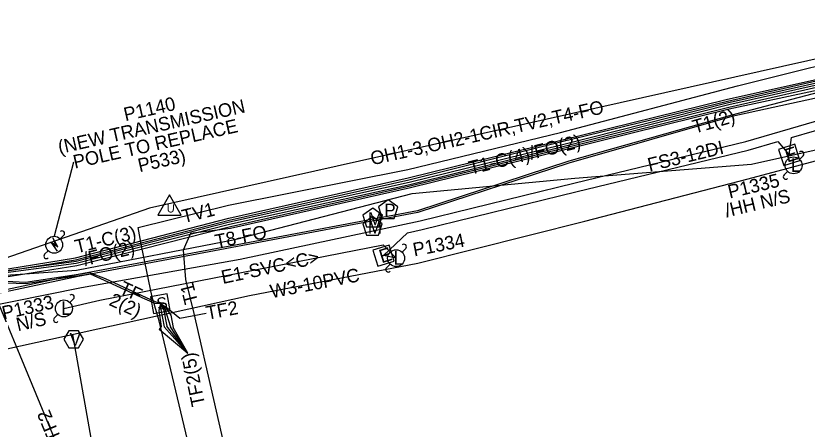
# Model space of a CAD drawing. Extents: x 2336688 to 2352634, y 362473 to 369571.
# Drawn here: x 2348017.1 to 2348250.9, y 367539 to 367661.1 of the extents above; entities that cross this region are included whole.
import ezdxf

# ---------------------------------------------------------------- set-up
doc = ezdxf.new("R2010")
doc.units = 0
for name, color, linetype in [('RD_EX_DV_Prop', 7, 'Continuous'), ('RD_EX_DV_TX_Prop', 7, 'Continuous'), ('RD_EX_RW', 7, 'Continuous'), ('RD_EX_RW_TX', 7, 'Continuous'), ('RD_HC_Data_Tic', 7, 'Continuous'), ('RD_PD_CstnLmt', 7, 'Continuous'), ('RD_PD_Final_TrvlWay', 7, 'Continuous'), ('RD_PD_FOC', 7, 'Continuous'), ('RD_PD_PatLn3', 7, 'Continuous'), ('RD_PD_PatLn4', 7, 'Continuous'), ('RD_SHT_ShtClip', 7, 'Continuous'), ('RD_Sketch1', 7, 'Continuous'), ('RD_Sketch2', 7, 'Continuous'), ('RD_Sketch5', 7, 'Continuous'), ('RD_Sketch8', 7, 'Continuous')]:
    doc.layers.add(name, color=color, linetype=linetype)

msp = doc.modelspace()

# ---------------------------------------------------------------- linework, layer by layer
at = {"layer": 'RD_EX_DV_TX_Prop'}
msp.add_line((2348034.1, 367617.92), (2348028.43, 367596), dxfattribs=at)
at = {"layer": 'RD_EX_RW_TX'}
for points in [[(2347868.44, 368054.11), (2347880, 368005.49), (2347890.68, 367955.5), (2347902.22, 367909.33), (2347920.64, 367859.94), (2347940.18, 367812), (2347959.68, 367768.1), (2347973.8, 367721.46), (2347979.06, 367711.04), (2347991.9, 367664.85), (2347998.75, 367622.27), (2348003.55, 367586.06), (2348009.9, 367584.2), (2348035.07, 367585.97), (2348081.85, 367595.07), (2348134.22, 367608.61), (2348182.28, 367613.21), (2348234.44, 367617.29), (2348281.25, 367627.74), (2348329.4, 367645.16), (2348376.54, 367659.65), (2348424.27, 367674.35), (2348472.98, 367689.81), (2348494.58, 367697.07)], [(2348085.42, 367455.46), (2348085.25, 367456.81), (2348084.11, 367472.36), (2348078.05, 367492.84), (2348059.44, 367571.03), (2348057.43, 367578.05), (2348054.24, 367593.15), (2348053.27, 367598.58), (2348079.95, 367605.18), (2348132.88, 367615.72), (2348177.98, 367626.63), (2348230.33, 367640.4), (2348274.48, 367651.48), (2348294.14, 367658.1), (2348322.12, 367668.38), (2348370.04, 367683.85), (2348388.49, 367688.84), (2348418.25, 367692.63), (2348451.32, 367697.47), (2348453.28, 367700.17), (2348444.65, 367725.62), (2348423.89, 367760.2), (2348406.22, 367798.41), (2348404.33, 367800.52)], [(2347889.37, 367561.99), (2347893.86, 367561.38), (2347925.12, 367563.83), (2347982.59, 367581.19), (2348034.77, 367589.67), (2348080.01, 367601.39), (2348132.99, 367613.3), (2348178.17, 367624.37), (2348226.99, 367636.38), (2348274.33, 367646.97), (2348277.67, 367644.22)], [(2348277.67, 367644.22), (2348273.84, 367645.8), (2348227.29, 367635.33), (2348178.6, 367623.03), (2348133.33, 367611.87), (2348080.21, 367600.2), (2348034.92, 367588.57), (2348009.29, 367585.15), (2347982.98, 367580.09), (2347935.21, 367568.08), (2347896.24, 367563.27), (2347883.18, 367561.78), (2347837.9, 367550.42), (2347785.45, 367539.42), (2347739.83, 367529.65), (2347687.13, 367520.3), (2347638.22, 367510.11), (2347594.98, 367500.2), (2347542.99, 367489.7), (2347493.07, 367480.59), (2347455.62, 367474.3)], [(2348273.75, 367646.44), (2348227.32, 367635.79), (2348178.43, 367623.86), (2348133.17, 367612.62), (2348080.1, 367600.69), (2348034.75, 367588.91), (2347982.83, 367580.63), (2347949.32, 367569.72), (2347947.83, 367569.22), (2347941.99, 367566.16), (2347925.16, 367563.38), (2347893.98, 367560.65), (2347889.37, 367561.99), (2347883.21, 367561.02), (2347838.01, 367549.55), (2347785.59, 367538.72), (2347739.47, 367528.78), (2347686.93, 367519.36), (2347638.55, 367509.72), (2347595.16, 367499.67), (2347542.86, 367488.84), (2347493.21, 367479.93), (2347455.71, 367473.66)], [(2347983.37, 367579.12), (2348035.16, 367587.36), (2348080.48, 367598.88), (2348133.65, 367610.87), (2348178.8, 367622), (2348227.72, 367634.18), (2348273.97, 367644.64)], [(2348008.15, 367584.51), (2348034.95, 367588.04), (2348080.24, 367599.59), (2348133.46, 367611.3), (2348178.72, 367622.57), (2348227.7, 367634.92), (2348273.91, 367645.31)], [(2348277.67, 367644.22), (2348273.99, 367643.66), (2348228.58, 367631.8), (2348180.44, 367618.2), (2348135.72, 367603.5), (2348082.46, 367593.52), (2348035.48, 367584.74), (2347984.84, 367574.01), (2347951.44, 367567.02), (2347939.95, 367565.03), (2347935.77, 367564.67), (2347885.73, 367554.51), (2347837.63, 367544.73), (2347786.79, 367534.85), (2347738.82, 367525.14), (2347722.47, 367522.46), (2347720.16, 367522.7), (2347718.41, 367521.27), (2347687.23, 367515.7), (2347639.77, 367505.05), (2347596.04, 367494.09), (2347543.53, 367483.61), (2347493.77, 367474.07), (2347444.64, 367465.68)], [(2348277.67, 367644.22), (2348274.19, 367643.16), (2348263.65, 367639.56), (2348260.75, 367638.41), (2348228.6, 367631.4), (2348180.48, 367617.57), (2348135.89, 367603.05), (2348082.6, 367592.95), (2348035.55, 367584.09), (2347984.98, 367573.4), (2347951.16, 367566.33), (2347935.9, 367564.13), (2347885.75, 367553.87), (2347837.61, 367543.77), (2347786.94, 367534.28), (2347738.95, 367524.48), (2347722.65, 367521.86), (2347718.4, 367520.47), (2347687.46, 367515.07), (2347596.2, 367493.52), (2347543.48, 367483.07), (2347493.75, 367473.66), (2347444.81, 367465.06)], [(2348277.67, 367644.22), (2348227.84, 367633.58), (2348178.94, 367621.43), (2348133.69, 367610.27), (2348080.57, 367598.27), (2348068.66, 367596.86), (2348066.5, 367591.91), (2348067.19, 367583.21), (2348069.73, 367573.23), (2348081.3, 367522.36), (2348088.83, 367494.16)]]:
    msp.add_lwpolyline(points, dxfattribs=at)
at = {"layer": 'RD_HC_Data_Tic'}
for p, q in [((2348248.64, 367618.72), (2348249.7, 367619.78)), ((2348244.05, 367614.13), (2348245.11, 367615.19)), ((2348030.21, 367595.27), (2348031.27, 367596.33)), ((2348025.61, 367590.68), (2348026.67, 367591.74)), ((2348131.22, 367591.32), (2348132.28, 367592.38)), ((2348126.62, 367586.72), (2348127.69, 367587.78)), ((2348033.07, 367576.46), (2348034.13, 367577.52)), ((2348028.47, 367571.86), (2348029.53, 367572.92))]:
    msp.add_line(p, q, dxfattribs=at)
msp.add_lwpolyline([(2348028.05, 367595.51), (2348028.87, 367593.5), (2348027.42, 367594.3), (2348029.29, 367591.62), (2348029.29, 367591.62), (2348028.09, 367593.72), (2348029.47, 367592.91)], close=True, dxfattribs=at)
for centre in [(2348246.88, 367616.96), (2348028.44, 367593.51), (2348129.45, 367589.55), (2348031.3, 367574.69)]:
    msp.add_circle(centre, 2.5, dxfattribs=at)
for centre, start, end in [((2348249.17, 367620.31), 315, 135), ((2348244.58, 367613.6), 135, 315), ((2348030.74, 367596.86), 315, 135), ((2348131.75, 367592.91), 315, 135), ((2348026.14, 367590.15), 135, 315), ((2348127.15, 367586.19), 135, 315), ((2348033.6, 367578.05), 315, 135), ((2348029, 367571.33), 135, 315)]:
    msp.add_arc(centre, 0.75, start, end, dxfattribs=at)
at = {"layer": 'RD_PD_Final_TrvlWay'}
msp.add_lwpolyline([(2348031.3, 367574.69), (2348041.95, 367577.13), (2348125.66, 367593.48), (2348129.45, 367589.55), (2348125.72, 367590.29), (2348132.8, 367597.05), (2348137.17, 367597.99), (2348182.97, 367609.24), (2348233.43, 367621.44), (2348242.25, 367624.01), (2348245.58, 367620.04), (2348246.3, 367625.19), (2348280.23, 367635.06), (2348327.01, 367648.97), (2348358.59, 367658.19), (2348362.96, 367652.69), (2348363.57, 367659.64), (2348375.35, 367663.08), (2348422.56, 367678.6), (2348465.74, 367693.2), (2348471.14, 367684.2), (2348470.93, 367694.95), (2348492.5, 367702.58)], dxfattribs=at)
for points in [[(2348247.21, 367623.18), (2348242.44, 367621.67), (2348243.95, 367616.91), (2348248.72, 367618.41)], [(2348127.35, 367593.42), (2348122.59, 367591.92), (2348124.09, 367587.15), (2348128.86, 367588.66)]]:
    msp.add_lwpolyline(points, close=True, dxfattribs=at)
at = {"layer": 'RD_PD_FOC'}
for p, q in [((2348067.87, 367561.42), (2348059.41, 367568.43)), ((2348067.87, 367561.42), (2348060.96, 367569.23)), ((2348067.87, 367561.46), (2348061.74, 367569.48)), ((2348067.87, 367561.42), (2348062.83, 367569.27)), ((2348067.87, 367561.46), (2348063.61, 367569.08))]:
    msp.add_line(p, q, dxfattribs=at)
at = {"layer": 'RD_PD_PatLn3'}
msp.add_lwpolyline([(2348062.47, 367608.24), (2348059.01, 367602.24), (2348065.94, 367602.24)], close=True, dxfattribs=at)
at = {"layer": 'RD_SHT_ShtClip'}
msp.add_line((2348006.83, 367588.44), (2348054.67, 367473.05), dxfattribs=at)
msp.add_lwpolyline([(2348302.69, 367654.16), (2348290.76, 367652.88), (2348289.31, 367651.06), (2348287.96, 367652.58), (2348257.65, 367649.33), (2348056.6, 367604.27), (2348013.81, 367589.41)], dxfattribs=at)
at = {"layer": 'RD_Sketch2'}
for points in [[(2347449.95, 367449.7), (2347496.38, 367458.28), (2347547.67, 367468.78), (2347595.96, 367479.29), (2347606, 367481.2), (2347641.64, 367490.61), (2347690.17, 367503.64), (2347702.37, 367506.83), (2347705.77, 367507.63), (2347740.68, 367513.89), (2347788.69, 367523.87), (2347838.62, 367531.94), (2347879.94, 367537.81), (2347883.63, 367538.5), (2347938.54, 367549.3), (2348009.43, 367561.67), (2348086.12, 367578.47), (2348135.82, 367588.03), (2348185.16, 367600.49), (2348233.5, 367612.99), (2348282.05, 367625.96)], [(2348033.84, 367567.03), (2348048.77, 367482.38), (2348049.97, 367475.89), (2348055.35, 367445.23), (2348062.4, 367417.46), (2348070.65, 367378.07), (2348085.84, 367331.58), (2348100.63, 367284.45), (2348116.51, 367235.46), (2348130.22, 367187.62), (2348142.11, 367135.45), (2348149.47, 367087.77), (2348154.82, 367039.58), (2348161.67, 366987.27), (2348162.16, 366984.87)]]:
    msp.add_lwpolyline(points, dxfattribs=at)
for points in [[(2348127.1, 367606.79), (2348124.2, 367604.68), (2348125.31, 367601.27), (2348128.9, 367601.27), (2348130, 367604.68)], [(2348122.53, 367604.33), (2348119.63, 367602.22), (2348120.74, 367598.81), (2348124.32, 367598.81), (2348125.43, 367602.22)], [(2348122.47, 367601.81), (2348119.57, 367599.7), (2348120.68, 367596.29), (2348124.26, 367596.29), (2348125.37, 367599.7)], [(2348037.07, 367565.6), (2348035.63, 367568.1), (2348032.74, 367568.1), (2348031.3, 367565.6), (2348032.74, 367563.1), (2348035.63, 367563.1)]]:
    msp.add_lwpolyline(points, close=True, dxfattribs=at)
at = {"layer": 'RD_Sketch5'}
msp.add_lwpolyline([(2347445.27, 367463.42), (2347494.44, 367469.25), (2347544.4, 367476.73), (2347594.33, 367486.36), (2347688.22, 367508.14), (2347739.9, 367520.09), (2347788.33, 367529.45), (2347838.31, 367540.64), (2347886.7, 367551.33), (2347928.19, 367559.84), (2347952.54, 367563.69), (2347985.72, 367570.62), (2348036.5, 367580.92), (2348083.37, 367589.22), (2348136.57, 367600.6), (2348182.34, 367611.84), (2348232.74, 367624.03), (2348279.47, 367637.63), (2348326.25, 367651.54), (2348374.55, 367665.64), (2348421.71, 367681.15), (2348468.93, 367697.05), (2348491.54, 367705.13)], dxfattribs=at)
at = {"layer": 'RD_Sketch8'}
for points in [[(2348006.44, 367588.48), (2348005.7, 367588.35), (2348006.64, 367586.78), (2348008.66, 367584.85), (2348011.35, 367582.82), (2348014.33, 367582.26), (2348020.03, 367582.02), (2348039.02, 367584.95), (2348043.19, 367583.03), (2348055.21, 367577.57), (2348058.18, 367576.27), (2348059.81, 367576.13)], [(2348006.44, 367588.48), (2348006.73, 367587.58), (2348011.23, 367583.23), (2348014.34, 367582.74), (2348019.96, 367582.43), (2348038.9, 367585.3), (2348043.5, 367583.53), (2348055.57, 367577.93), (2348058.42, 367576.65), (2348059.81, 367576.13)], [(2348059.81, 367576.13), (2348059.33, 367574.11), (2348060.02, 367569.4), (2348059.41, 367568.43)], [(2348059.81, 367576.13), (2348061.77, 367574.9), (2348065.6, 367571.85), (2348073.32, 367573.29)], [(2348059.81, 367576.13), (2348061.46, 367574.77), (2348062.9, 367572.69), (2348063.61, 367569.08)], [(2348059.81, 367576.13), (2348061.13, 367574.58), (2348062.83, 367569.27)], [(2348059.81, 367576.13), (2348059.95, 367574.4), (2348060.96, 367569.23)], [(2348059.81, 367576.13), (2348060.71, 367574.46), (2348061.74, 367569.48)]]:
    msp.add_lwpolyline(points, dxfattribs=at)
msp.add_lwpolyline([(2348061.82, 367579.04), (2348056.9, 367578.13), (2348057.81, 367573.21), (2348062.72, 367574.12)], close=True, dxfattribs=at)

# ---------------------------------------------------------------- texts
at = {"layer": 'RD_EX_DV_Prop'}
msp.add_text('E1-SVC<C>', height=4, rotation=12.0714, dxfattribs=at).set_placement((2348078.26, 367581.9))
at = {"layer": 'RD_EX_DV_TX_Prop'}
for s, rotation, p in [('(NEW TRANSMISSION', 12.6337, (2348030.06, 367620.3)), ('P1140', 12.6337, (2348049.47, 367629.99)), ('POLE TO REPLACE', 12.6337, (2348034.54, 367615.97)), ('P533)', 12.6337, (2348053.66, 367614.92)), ('P1335', 13.4802, (2348227.99, 367607.14)), ('/HH N/S', 13.4802, (2348227.12, 367601.57)), ('P1334', 11.0518, (2348134.82, 367590.04)), ('P1333', 12.8877, (2348013.52, 367571.34)), ('N/S', 12.8877, (2348017.72, 367567.91))]:
    msp.add_text(s, height=4, rotation=rotation, dxfattribs=at).set_placement(p)
at = {"layer": 'RD_EX_RW'}
for s, rotation, p in [('T1(2)', 16.0372, (2348217.66, 367626.3)), ('T1-C(4)/FO(2)', 13.8405, (2348151.45, 367614.17)), ('TV1', 13.9038, (2348066.7, 367599.84)), ('T1-C(3)', 13.8405, (2348035.1, 367590.93)), ('T8-FO', 11.0734, (2348076.35, 367592.49)), ('/FO(2)', 13.8405, (2348037.58, 367587.21)), ('T1', 104.2506, (2348070.95, 367576.53))]:
    msp.add_text(s, height=4, rotation=rotation, dxfattribs=at).set_placement(p)
at = {"layer": 'RD_HC_Data_Tic'}
for p in [(2348246.07, 367615.02), (2348128.64, 367587.62), (2348030.49, 367572.76)]:
    msp.add_text('L', height=4, rotation=360, dxfattribs=at).set_placement(p)
at = {"layer": 'RD_PD_CstnLmt'}
msp.add_text('W3-10PVC', height=4, rotation=10.8923, dxfattribs=at).set_placement((2348092.65, 367577.69))
at = {"layer": 'RD_PD_Final_TrvlWay'}
for p in [(2348245.03, 367617.77), (2348125.17, 367588.01)]:
    msp.add_text('E', height=4, rotation=17.5359, dxfattribs=at).set_placement(p)
at = {"layer": 'RD_PD_FOC'}
for s, rotation, p in [('TF', 335.5769, (2348047.33, 367579.26)), ('2(2)', 335.5769, (2348044.36, 367575.78)), ('TF2', 10.5614, (2348073.69, 367571.33)), ('TF2(5)', 101.6966, (2348073.06, 367546.22))]:
    msp.add_text(s, height=4, rotation=rotation, dxfattribs=at).set_placement(p)
at = {"layer": 'RD_PD_PatLn3'}
msp.add_text('U', height=2.4, dxfattribs=at).set_placement((2348061.72, 367603.04))
at = {"layer": 'RD_PD_PatLn4'}
for s, rotation, p in [('OH1-3,OH2-1CIR,TV2,T4-FO', 12.6337, (2348122.35, 367616.96)), ('TF2', 112.5189, (2348030.59, 367536.34))]:
    msp.add_text(s, height=4, rotation=rotation, dxfattribs=at).set_placement(p)
at = {"layer": 'RD_Sketch1'}
msp.add_text('FS3-12DI', height=4, rotation=13.5954, dxfattribs=at).set_placement((2348204.3, 367615.09))
at = {"layer": 'RD_Sketch2'}
msp.add_text('P', height=3.75, rotation=360, dxfattribs=at).set_placement((2348125.95, 367601.87))
for s, p in [('M', (2348121.16, 367599.29)), ('M', (2348121.1, 367596.77)), ('V', (2348032.98, 367563.72))]:
    msp.add_text(s, height=3.75, dxfattribs=at).set_placement(p)
at = {"layer": 'RD_Sketch8'}
msp.add_text('S', height=3.53, rotation=10.4256, dxfattribs=at).set_placement((2348059.06, 367574.19))

doc.saveas('drawing.dxf')
